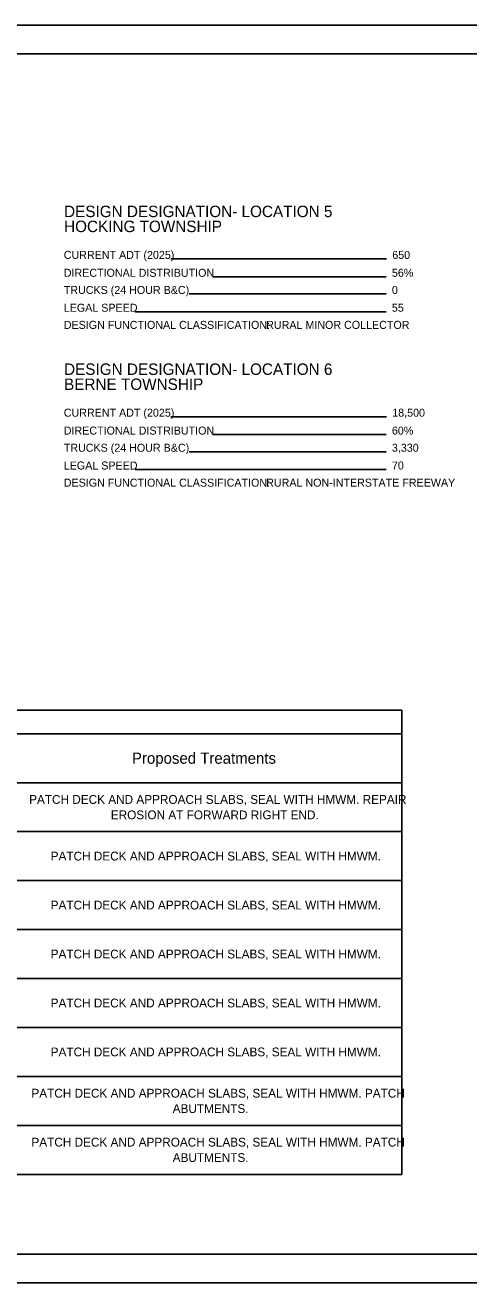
# Model space of a CAD drawing. Extents: x -51.9 to 34, y 0 to 23.3.
# Drawn here: x 14.66 to 22.42, y 0 to 22 of the extents above; entities that cross this region are included whole.
import ezdxf

# ---------------------------------------------------------------- set-up
doc = ezdxf.new("R2010")
doc.units = 0
for name, color, linetype in [('SH_Border', 7, 'Continuous'), ('SH_Cut_Line', 7, 'Continuous'), ('SH_Data', 7, 'Continuous'), ('SH_Text', 7, 'Continuous')]:
    doc.layers.add(name, color=color, linetype=linetype)

msp = doc.modelspace()

# ---------------------------------------------------------------- linework, layer by layer
at = {"layer": 'SH_Border'}
msp.add_lwpolyline([(1.5, 21.5), (33.5, 21.5), (33.5, 0.5), (1.5, 0.5)], close=True, dxfattribs=at)
at = {"layer": 'SH_Cut_Line'}
msp.add_lwpolyline([(0, 0), (34, 0), (34, 22), (0, 22)], close=True, dxfattribs=at)
at = {"layer": 'SH_Data'}
for p, q in [((20.984, 17.911), (17.212, 17.911)), ((20.978, 17.598), (17.945, 17.598)), ((20.978, 17.298), (17.53, 17.298)), ((20.978, 16.987), (16.584, 16.987)), ((20.984, 15.151), (17.212, 15.151)), ((20.978, 14.838), (17.945, 14.838)), ((20.978, 14.538), (17.53, 14.538)), ((20.978, 14.227), (16.584, 14.227))]:
    msp.add_line(p, q, dxfattribs=at)
at = {"layer": 'SH_Text'}
for p, q in [((2.41, 10.018), (21.252, 10.018)), ((21.252, 10.018), (21.252, 1.898)), ((2.41, 9.606), (21.252, 9.606)), ((2.41, 8.749), (21.252, 8.749)), ((2.41, 7.893), (21.252, 7.893)), ((2.41, 7.036), (21.252, 7.036)), ((2.41, 6.18), (21.252, 6.18)), ((2.41, 5.323), (21.252, 5.323)), ((2.41, 4.467), (21.252, 4.467)), ((2.41, 3.611), (21.252, 3.611)), ((2.41, 2.754), (21.252, 2.754)), ((2.41, 1.898), (21.252, 1.898))]:
    msp.add_line(p, q, dxfattribs=at)

# ---------------------------------------------------------------- texts
at = {"layer": 'SH_Data'}
for s, p in [('DESIGN DESIGNATION- LOCATION 5', (15.341, 18.642)), ('HOCKING TOWNSHIP', (15.341, 18.38)), ('DESIGN DESIGNATION- LOCATION 6', (15.341, 15.882)), ('BERNE TOWNSHIP', (15.341, 15.619))]:
    msp.add_text(s, height=0.2, dxfattribs=at).set_placement(p)
at = {"layer": 'SH_Text'}
for s, height, p in [('CURRENT ADT (2025)', 0.14, (15.336, 17.911)), ('650', 0.14, (21.084, 17.911)), ('DIRECTIONAL DISTRIBUTION', 0.14, (15.336, 17.598)), ('56%', 0.14, (21.078, 17.598)), ('TRUCKS (24 HOUR B&C)', 0.14, (15.336, 17.298)), ('0', 0.14, (21.078, 17.298)), ('LEGAL SPEED', 0.14, (15.336, 16.987)), ('55', 0.14, (21.078, 16.987)), ('DESIGN FUNCTIONAL CLASSIFICATION:', 0.14, (15.336, 16.687)), ('RURAL MINOR COLLECTOR', 0.14, (18.878, 16.687)), ('CURRENT ADT (2025)', 0.14, (15.336, 15.151)), ('18,500', 0.14, (21.084, 15.151)), ('DIRECTIONAL DISTRIBUTION', 0.14, (15.336, 14.838)), ('60%', 0.14, (21.078, 14.838)), ('TRUCKS (24 HOUR B&C)', 0.14, (15.336, 14.538)), ('3,330', 0.14, (21.078, 14.538)), ('LEGAL SPEED', 0.14, (15.336, 14.227)), ('70', 0.14, (21.078, 14.227)), ('DESIGN FUNCTIONAL CLASSIFICATION:', 0.14, (15.336, 13.927)), ('RURAL NON-INTERSTATE FREEWAY', 0.14, (18.878, 13.927)), ('Proposed Treatments', 0.196, (16.529, 9.08)), ('PATCH DECK AND APPROACH SLABS, SEAL WITH HMWM. REPAIR ', 0.154, (14.73, 8.379)), ('EROSION AT FORWARD RIGHT END.', 0.154, (16.159, 8.109)), ('PATCH DECK AND APPROACH SLABS, SEAL WITH HMWM.', 0.154, (15.107, 7.388)), ('PATCH DECK AND APPROACH SLABS, SEAL WITH HMWM.', 0.154, (15.107, 6.531)), ('PATCH DECK AND APPROACH SLABS, SEAL WITH HMWM.', 0.154, (15.107, 5.675)), ('PATCH DECK AND APPROACH SLABS, SEAL WITH HMWM.', 0.154, (15.107, 4.818)), ('PATCH DECK AND APPROACH SLABS, SEAL WITH HMWM.', 0.154, (15.107, 3.962)), ('PATCH DECK AND APPROACH SLABS, SEAL WITH HMWM. PATCH ', 0.154, (14.77, 3.24)), ('ABUTMENTS.', 0.154, (17.242, 2.971)), ('PATCH DECK AND APPROACH SLABS, SEAL WITH HMWM. PATCH ', 0.154, (14.77, 2.384)), ('ABUTMENTS.', 0.154, (17.242, 2.114))]:
    msp.add_text(s, height=height, dxfattribs=at).set_placement(p)

doc.saveas('drawing.dxf')
